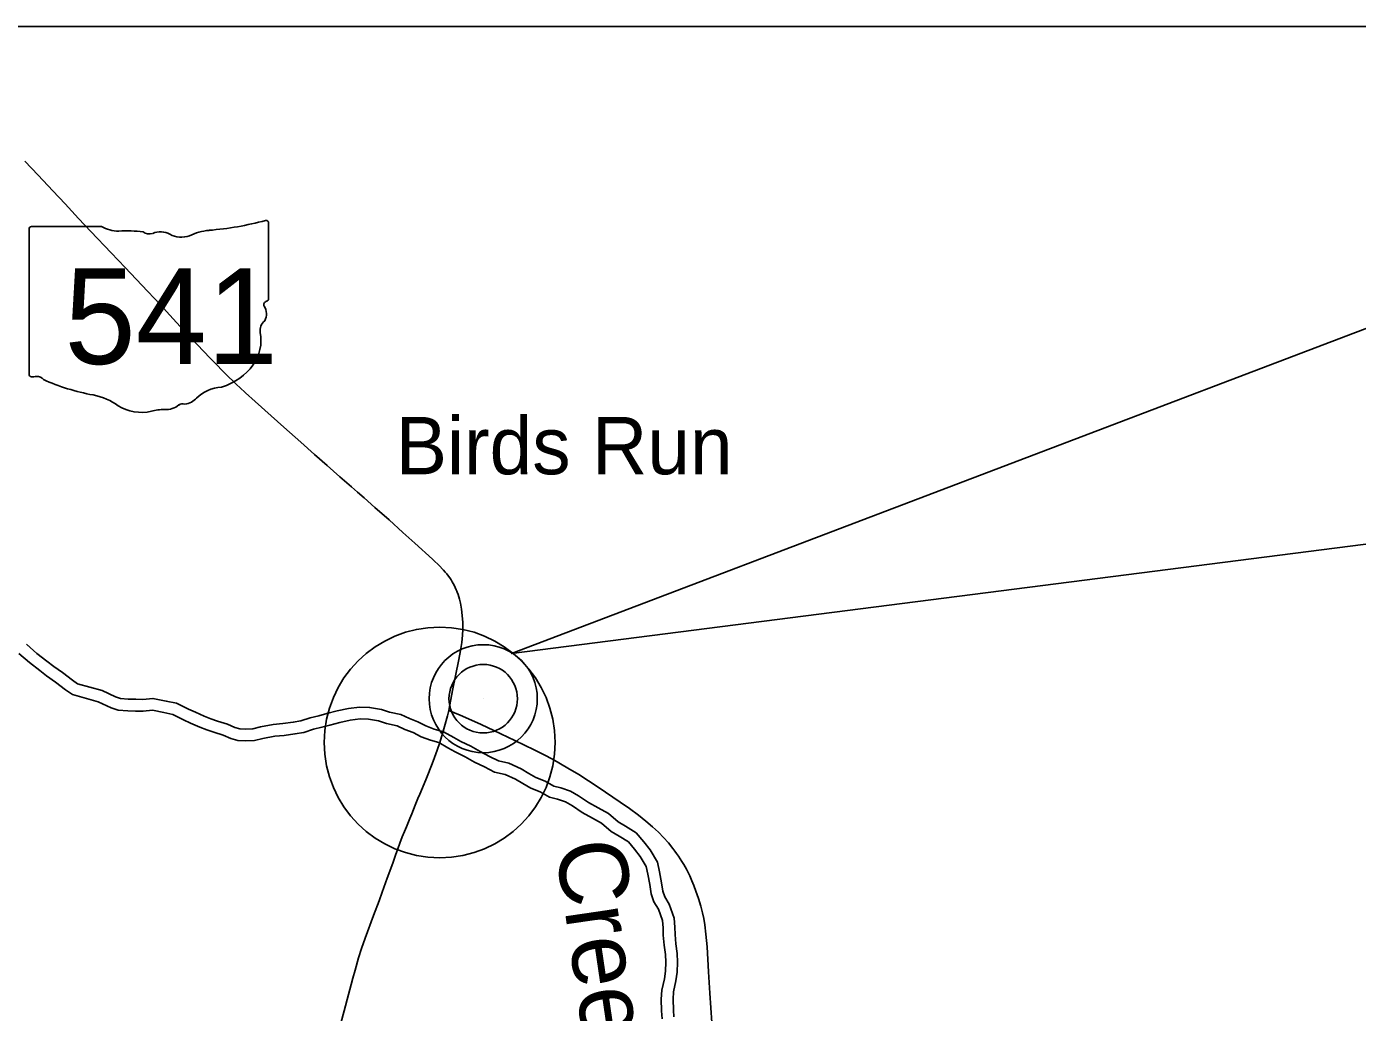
# Model space of a CAD drawing. Extents: x -12.1 to 34, y 0 to 22.
# Drawn here: x -10.595 to -8.877, y 19.033 to 20.306 of the extents above; entities that cross this region are included whole.
import ezdxf

# ---------------------------------------------------------------- set-up
doc = ezdxf.new("R2010")
doc.units = 0
for name, color, linetype in [('BR_P_Gen_Text', 7, 'Continuous'), ('Default', 7, 'Continuous'), ('GM_X_Major_River', 7, 'Continuous'), ('GM_X_Major_River_Text', 7, 'Continuous'), ('GM_X_State_Route', 7, 'Continuous'), ('GM_X_State_Shield', 7, 'Continuous'), ('GM_X_Unincorporated', 7, 'Continuous'), ('GM_X_Unincorporated_Location', 7, 'Continuous'), ('GM_X_Unincorporated_Text', 7, 'Continuous'), ('SH_Text', 7, 'Continuous')]:
    doc.layers.add(name, color=color, linetype=linetype)

msp = doc.modelspace()

# ---------------------------------------------------------------- linework, layer by layer
at = {"layer": 'BR_P_Gen_Text'}
msp.add_lwpolyline([(-8.7792, 19.9493), (-8.7792, 19.649), (-9.9694, 19.4964)], close=True, dxfattribs=at)
at = {"layer": 'Default'}
msp.add_circle((-10.0621, 19.3816), 0.149, dxfattribs=at)
at = {"layer": 'GM_X_Major_River'}
for points in [[(-9.7597, 19.027), (-9.7604, 19.0359), (-9.7609, 19.0499), (-9.7604, 19.0596), (-9.7571, 19.0736), (-9.7556, 19.0849), (-9.7549, 19.0976), (-9.7555, 19.1091), (-9.7574, 19.1213), (-9.7582, 19.1336), (-9.7586, 19.143), (-9.7596, 19.1548), (-9.7659, 19.1726), (-9.7716, 19.1822), (-9.7742, 19.1894), (-9.7756, 19.2004), (-9.7783, 19.2145), (-9.7811, 19.2271), (-9.7905, 19.2427), (-9.7987, 19.2532), (-9.8083, 19.2647), (-9.8222, 19.2734), (-9.8316, 19.2791), (-9.8443, 19.2898), (-9.8575, 19.2973), (-9.8701, 19.3039), (-9.8827, 19.3125), (-9.8934, 19.3188), (-9.9057, 19.3229), (-9.9147, 19.3253), (-9.9259, 19.3315), (-9.9379, 19.3363), (-9.9472, 19.3416), (-9.957, 19.3475), (-9.9727, 19.3548), (-9.986, 19.3578), (-9.9976, 19.3636), (-10.01, 19.3697), (-10.0221, 19.3767), (-10.035, 19.383), (-10.0438, 19.388), (-10.0572, 19.3955), (-10.0694, 19.3989), (-10.0799, 19.4029), (-10.0902, 19.4084), (-10.1009, 19.4124), (-10.1123, 19.4178), (-10.1267, 19.4206), (-10.1372, 19.4241), (-10.1526, 19.4269), (-10.1655, 19.4272), (-10.18, 19.4254), (-10.1944, 19.4223), (-10.208, 19.4188), (-10.2181, 19.4159), (-10.2293, 19.4133), (-10.2412, 19.4094), (-10.2512, 19.4077), (-10.2644, 19.4059), (-10.2771, 19.4047), (-10.2936, 19.4018), (-10.3035, 19.3991), (-10.3127, 19.3988), (-10.3201, 19.3992), (-10.3266, 19.4009), (-10.3362, 19.4053), (-10.349, 19.4093), (-10.3575, 19.4122), (-10.3661, 19.4155), (-10.3774, 19.4205), (-10.3863, 19.4245), (-10.4017, 19.4322), (-10.415, 19.435), (-10.4323, 19.4385), (-10.4453, 19.4372), (-10.4543, 19.4374), (-10.4642, 19.4377), (-10.4742, 19.4384), (-10.4805, 19.4407), (-10.4977, 19.4485), (-10.5295, 19.4574), (-10.5363, 19.4621), (-10.5491, 19.4718), (-10.5604, 19.4798), (-10.5691, 19.4866), (-10.582, 19.4965), (-10.5955, 19.5084)], [(-9.7597, 19.027), (-9.7604, 19.0359), (-9.7609, 19.0499), (-9.7604, 19.0596), (-9.7571, 19.0736), (-9.7556, 19.0849), (-9.7549, 19.0976), (-9.7555, 19.1091), (-9.7574, 19.1213), (-9.7582, 19.1336), (-9.7586, 19.143), (-9.7596, 19.1548), (-9.7659, 19.1726), (-9.7716, 19.1822), (-9.7742, 19.1894), (-9.7756, 19.2004), (-9.7783, 19.2145), (-9.7811, 19.2271), (-9.7905, 19.2427), (-9.7987, 19.2532), (-9.8083, 19.2647), (-9.8222, 19.2734), (-9.8316, 19.2791), (-9.8443, 19.2898), (-9.8575, 19.2973), (-9.8701, 19.3039), (-9.8827, 19.3125), (-9.8934, 19.3188), (-9.9057, 19.3229), (-9.9147, 19.3253), (-9.9259, 19.3315), (-9.9379, 19.3363), (-9.9472, 19.3416), (-9.957, 19.3475), (-9.9727, 19.3548), (-9.986, 19.3578), (-9.9976, 19.3636), (-10.01, 19.3697), (-10.0221, 19.3767), (-10.035, 19.383), (-10.0438, 19.388), (-10.0572, 19.3955), (-10.0694, 19.3989), (-10.0799, 19.4029), (-10.0902, 19.4084), (-10.1009, 19.4124), (-10.1123, 19.4178), (-10.1267, 19.4206), (-10.1372, 19.4241), (-10.1526, 19.4269), (-10.1655, 19.4272), (-10.18, 19.4254), (-10.1944, 19.4223), (-10.208, 19.4188), (-10.2181, 19.4159), (-10.2293, 19.4133), (-10.2412, 19.4094), (-10.2512, 19.4077), (-10.2644, 19.4059), (-10.2771, 19.4047), (-10.2936, 19.4018), (-10.3035, 19.3991), (-10.3127, 19.3988), (-10.3201, 19.3992), (-10.3266, 19.4009), (-10.3362, 19.4053), (-10.349, 19.4093), (-10.3575, 19.4122), (-10.3661, 19.4155), (-10.3774, 19.4205), (-10.3863, 19.4245), (-10.4017, 19.4322), (-10.415, 19.435), (-10.4323, 19.4385), (-10.4453, 19.4372), (-10.4543, 19.4374), (-10.4642, 19.4377), (-10.4742, 19.4384), (-10.4805, 19.4407), (-10.4977, 19.4485), (-10.5295, 19.4574), (-10.5363, 19.4621), (-10.5491, 19.4718), (-10.5604, 19.4798), (-10.5691, 19.4866), (-10.582, 19.4965), (-10.5952, 19.5081)], [(-9.7748, 19.0248), (-9.7756, 19.0351), (-9.7761, 19.05), (-9.7755, 19.0617), (-9.7721, 19.0763), (-9.7708, 19.0863), (-9.7702, 19.0976), (-9.7707, 19.1076), (-9.7725, 19.1196), (-9.7734, 19.1328), (-9.7738, 19.142), (-9.7746, 19.1516), (-9.7797, 19.1661), (-9.7855, 19.1756), (-9.7891, 19.1859), (-9.7907, 19.198), (-9.7933, 19.2114), (-9.7955, 19.2214), (-9.8031, 19.2341), (-9.8106, 19.2436), (-9.8185, 19.2531), (-9.8302, 19.2604), (-9.8406, 19.2667), (-9.8531, 19.2773), (-9.8648, 19.2839), (-9.878, 19.2909), (-9.8908, 19.2996), (-9.8997, 19.3049), (-9.9101, 19.3083), (-9.9204, 19.311), (-9.9325, 19.3177), (-9.9446, 19.3225), (-9.9549, 19.3285), (-9.9642, 19.3341), (-9.9777, 19.3403), (-9.9912, 19.3434), (-10.0043, 19.35), (-10.0172, 19.3563), (-10.0293, 19.3632), (-10.0421, 19.3695), (-10.0514, 19.3747), (-10.0631, 19.3814), (-10.0741, 19.3845), (-10.0862, 19.3889), (-10.0965, 19.3945), (-10.1069, 19.3983), (-10.1172, 19.4032), (-10.1307, 19.4059), (-10.141, 19.4094), (-10.1541, 19.4117), (-10.1647, 19.412), (-10.1775, 19.4104), (-10.1909, 19.4074), (-10.204, 19.4041), (-10.2142, 19.4012), (-10.2252, 19.3986), (-10.2376, 19.3946), (-10.2489, 19.3927), (-10.2627, 19.3907), (-10.2751, 19.3896), (-10.2903, 19.3869), (-10.3012, 19.384), (-10.3129, 19.3835), (-10.3225, 19.3841), (-10.3317, 19.3865), (-10.3417, 19.391), (-10.3538, 19.3948), (-10.3627, 19.3979), (-10.3719, 19.4014), (-10.3836, 19.4066), (-10.3929, 19.4108), (-10.4068, 19.4177), (-10.4181, 19.4201), (-10.433, 19.4231), (-10.4447, 19.422), (-10.4546, 19.4222), (-10.4649, 19.4225), (-10.4773, 19.4234), (-10.4862, 19.4265), (-10.5029, 19.4342), (-10.536, 19.4434), (-10.5453, 19.4497), (-10.5581, 19.4595), (-10.5695, 19.4676), (-10.5785, 19.4746), (-10.5917, 19.4847), (-10.6052, 19.4967)]]:
    msp.add_lwpolyline(points, dxfattribs=at)
at = {"layer": 'GM_X_State_Route'}
for points in [[(-10.5978, 20.1324), (-10.5805, 20.1142), (-10.5613, 20.094), (-10.5458, 20.0773), (-10.5283, 20.0585), (-10.5124, 20.0416), (-10.4862, 20.0142), (-10.4682, 19.9951), (-10.4466, 19.9723), (-10.423, 19.9473), (-10.406, 19.9288), (-10.3922, 19.9139), (-10.375, 19.8957), (-10.3582, 19.8779), (-10.3541, 19.8737), (-10.3387, 19.8579), (-10.325, 19.8445), (-10.3137, 19.8341), (-10.3126, 19.833), (-10.3005, 19.8221), (-10.2796, 19.8036), (-10.2631, 19.7888), (-10.2415, 19.7693), (-10.2236, 19.7536), (-10.2075, 19.7393), (-10.1909, 19.7246), (-10.1759, 19.7117), (-10.1681, 19.7048), (-10.1598, 19.6974), (-10.1458, 19.6851), (-10.1274, 19.669), (-10.1097, 19.653), (-10.0943, 19.6388), (-10.0713, 19.6182), (-10.0698, 19.6167), (-10.0633, 19.6105), (-10.0573, 19.6041), (-10.055, 19.6017), (-10.053, 19.5993), (-10.0508, 19.5966), (-10.049, 19.5941), (-10.0475, 19.5918), (-10.0459, 19.5892), (-10.0446, 19.5869), (-10.0434, 19.5846), (-10.042, 19.5817), (-10.0407, 19.5787), (-10.0401, 19.5772)], [(-10.0401, 19.5772), (-10.0394, 19.5757), (-10.0384, 19.5727), (-10.0364, 19.5665), (-10.0352, 19.5614), (-10.0338, 19.5539), (-10.0329, 19.5457), (-10.0323, 19.5364), (-10.0322, 19.532), (-10.0323, 19.5276), (-10.0326, 19.52), (-10.0336, 19.5107), (-10.0352, 19.5002), (-10.0373, 19.4888), (-10.0455, 19.4488), (-10.0489, 19.43), (-10.0501, 19.423)], [(-10.1897, 19.019), (-10.1854, 19.035), (-10.1799, 19.0562), (-10.1765, 19.0689), (-10.1743, 19.0772), (-10.1713, 19.0875), (-10.1667, 19.1034), (-10.1631, 19.1154), (-10.1583, 19.1286), (-10.1474, 19.1581), (-10.1404, 19.1769), (-10.1364, 19.188), (-10.1299, 19.2063), (-10.1266, 19.2155), (-10.1223, 19.2271), (-10.1191, 19.2358), (-10.1161, 19.2443), (-10.1136, 19.2517), (-10.1104, 19.2598), (-10.1074, 19.2667), (-10.105, 19.2727), (-10.1008, 19.2833), (-10.0982, 19.2894), (-10.0938, 19.3006), (-10.092, 19.3048), (-10.0902, 19.3093), (-10.0879, 19.3146), (-10.0844, 19.3231), (-10.0793, 19.3354), (-10.0717, 19.354), (-10.0688, 19.3621), (-10.0653, 19.3717), (-10.0621, 19.3816), (-10.0584, 19.3933), (-10.0559, 19.402), (-10.052, 19.4161), (-10.0501, 19.423)], [(-10.0501, 19.423), (-10.0355, 19.417), (-10.0135, 19.4071), (-10.0084, 19.4048), (-9.9921, 19.3971), (-9.9653, 19.3842), (-9.94, 19.3722), (-9.9281, 19.3661), (-9.9157, 19.3595), (-9.8965, 19.3485), (-9.8826, 19.34), (-9.8577, 19.3237), (-9.8291, 19.3046), (-9.8171, 19.2963), (-9.8054, 19.2876), (-9.7959, 19.2799), (-9.7874, 19.2726), (-9.7797, 19.2655), (-9.7732, 19.2588), (-9.7669, 19.2518), (-9.761, 19.2446), (-9.7586, 19.2413), (-9.7562, 19.2381), (-9.7539, 19.2347), (-9.7516, 19.2314), (-9.7495, 19.228), (-9.747, 19.2241), (-9.7452, 19.2211), (-9.7435, 19.218), (-9.7416, 19.2144), (-9.7404, 19.2118), (-9.7393, 19.2095), (-9.7382, 19.207), (-9.7364, 19.2027), (-9.734, 19.1967), (-9.7313, 19.1896), (-9.7281, 19.1802), (-9.725, 19.1702), (-9.7228, 19.1617), (-9.7213, 19.1542), (-9.7199, 19.1462), (-9.7184, 19.134), (-9.717, 19.1177), (-9.7149, 19.0852), (-9.7132, 19.0578), (-9.7096, 19.0008)]]:
    msp.add_lwpolyline(points, dxfattribs=at)
at = {"layer": 'GM_X_State_Shield'}
for p, q in [((-10.2831, 19.9546), (-10.2831, 20.0528)), ((-10.5921, 20.0449), (-10.5921, 19.8573)), ((-10.4985, 20.0481), (-10.589, 20.0481)), ((-10.2831, 19.9547), (-10.2831, 19.9546))]:
    msp.add_line(p, q, dxfattribs=at)
for centre, major_axis, start_param, end_param in [((-10.3932, 20.3039), (0.3277, 0), 4.814394, 5.042369), ((-10.2865, 20.0532), (0.00344, 0), 6.141152, 7.989035), ((-10.5885, 20.0453), (0.00358, 0), 1.712693, 3.28349), ((-10.477, 20.0699), (0.0347, 0), 4.042523, 4.731795), ((-10.4655, 19.9428), (0.1246, 0), 1.404758, 1.657858), ((-10.4372, 20.0463), (0.01, 0), 3.836095, 5.185415), ((-10.4225, 20.0246), (0.0208, 0), 0.950623, 2.079405), ((-10.3956, 20.0543), (0.0251, 0), 4.081561, 5.145723), ((-10.3514, 19.9908), (0.0659, 0), 1.699011, 2.107814), ((-10.2839, 19.9474), (0.00532, 0), 1.883978, 3.671073), ((-10.3178, 19.935), (0.032, 0), 5.934695, 6.695948), ((-10.2868, 19.9543), (0.00368, 0), 5.05454, 6.418171), ((-10.3748, 19.9011), (0.082, 0), 5.101752, 6.440018), ((-10.2708, 19.9136), (0.0232, 0), 2.387724, 3.262537), ((-10.5885, 19.8569), (0.00361, 0), 3.00124, 4.508301), ((-10.588, 19.8761), (0.0276, 0), 4.665946, 4.897461), ((-10.5823, 19.8465), (0.00994, 0), 0.519207, 1.627899), ((-10.4569, 20.015), (0.2366, 0), 4.195997, 4.488961), ((-10.5274, 19.773), (0.074, 0), 0.823519, 1.323587), ((-10.3971, 19.8391), (0.0265, 0), 4.937069, 5.64225), ((-10.3402, 19.8046), (0.0449, 0), 1.647645, 2.488434), ((-10.4473, 19.8455), (0.047, 0), 4.026481, 4.996735), ((-10.4202, 19.7807), (0.0386, 0), 1.495662, 1.94098), ((-10.4168, 19.8315), (0.025, 0), 4.691044, 5.507374), ((-10.3941, 19.8133), (0.00705, 0), 1.147584, 2.315152)]:
    msp.add_ellipse(centre, major_axis=major_axis, ratio=0.8, start_param=start_param, end_param=end_param, dxfattribs=at)
at = {"layer": 'GM_X_Unincorporated'}
for radius in [0.0698, 0.0442]:
    msp.add_circle((-10.0059, 19.4381), radius, dxfattribs=at)
at = {"layer": 'GM_X_Unincorporated_Location'}
msp.add_line((-10.0059, 19.4381), (-10.0059, 19.4381), dxfattribs=at)
at = {"layer": 'SH_Text'}
msp.add_lwpolyline([(-12.1463, 20.3063), (-4.4383, 20.3063), (-4.4383, 10.9773), (-12.1463, 10.9773)], close=True, dxfattribs=at)

# ---------------------------------------------------------------- texts
at = {"layer": 'GM_X_Major_River_Text'}
msp.add_text('Creek', height=0.08872, rotation=278.3514, dxfattribs=at).set_placement((-9.9133, 19.25))
at = {"layer": 'GM_X_State_Shield'}
msp.add_text('541', height=0.1236, dxfattribs=at).set_placement((-10.5465, 19.8705))
at = {"layer": 'GM_X_Unincorporated_Text'}
msp.add_text('Birds Run', height=0.07404, rotation=0, dxfattribs=at).set_placement((-10.1187, 19.728))

doc.saveas('drawing.dxf')
